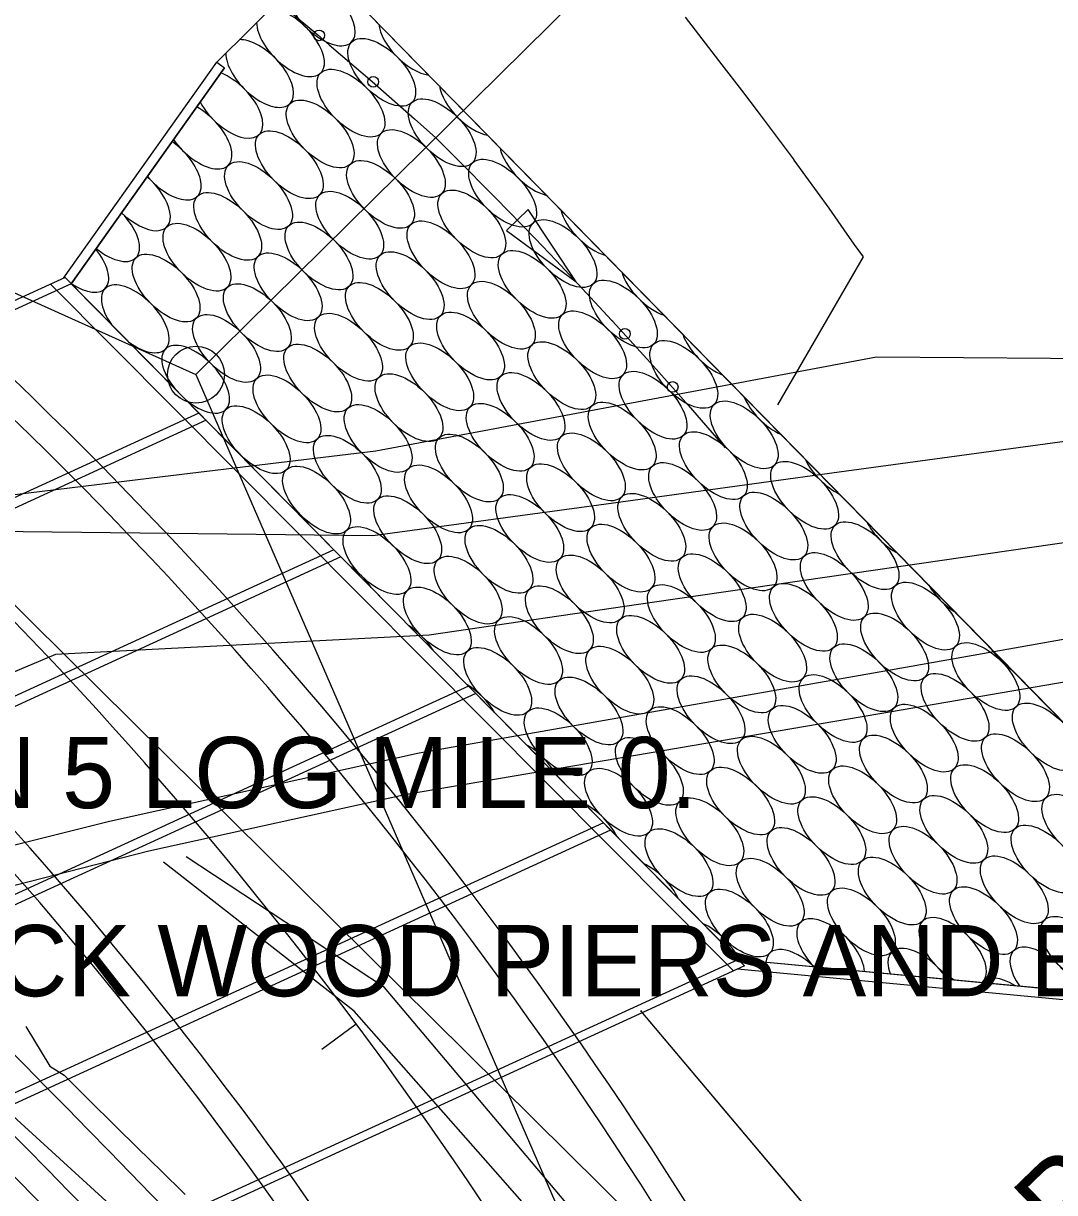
# Model space of a CAD drawing. Extents: x 1660112 to 1662239, y 668919 to 671377.
# Drawn here: x 1661310.6 to 1661383, y 670229.8 to 670311.9 of the extents above; entities that cross this region are included whole.
import ezdxf

# ---------------------------------------------------------------- set-up
doc = ezdxf.new("R2010")
doc.units = 0
for name, color, linetype in [('R_Concrete', 7, 'Continuous'), ('R_Concrete Hidden', 7, 'Continuous'), ('R_Horz Alg', 7, 'Continuous'), ('R_Horz Alg Annot', 7, 'Continuous'), ('R_Proposed Const Limits_Hand', 7, 'Continuous'), ('R_Proposed Road_Lane', 7, 'Continuous'), ('R_Proposed Road_Shoulder', 7, 'Continuous'), ('R_Water', 7, 'Continuous'), ('R_Water Annot', 7, 'Continuous'), ('S_BASELINE', 7, 'Continuous'), ('S_DITCHLINE', 7, 'Continuous'), ('S_EDGE_PAVEMENT', 7, 'Continuous'), ('S_EXIST_ROW', 7, 'Continuous'), ('S_FENCE', 7, 'Continuous'), ('S_LOG_MILE_ANNOT', 7, 'Continuous'), ('S_MSC_PT_SYM', 7, 'Continuous'), ('S_STREAM', 7, 'Continuous'), ('S_SURVEY_TEXT_ANNOT', 7, 'Continuous')]:
    doc.layers.add(name, color=color, linetype=linetype)

msp = doc.modelspace()

# ---------------------------------------------------------------- linework, layer by layer
at = {"layer": 'R_Concrete'}
for p, q in [((1661313.385, 670294.038), (1661324.141, 670309.192)), ((1661313.385, 670294.038), (1661324.141, 670309.192)), ((1661313.922, 670293.642), (1661324.685, 670308.806)), ((1661313.922, 670293.642), (1661324.685, 670308.806)), ((1661324.141, 670309.192), (1661324.685, 670308.806)), ((1661324.141, 670309.192), (1661324.685, 670308.806)), ((1661313.486, 670294.084), (1661236.073, 670258.587)), ((1661313.486, 670294.084), (1661236.073, 670258.587)), ((1661361.211, 670245.744), (1661313.486, 670294.084)), ((1661361.211, 670245.744), (1661313.486, 670294.084)), ((1661312.468, 670293.617), (1661360.441, 670245.391)), ((1661312.468, 670293.617), (1661360.441, 670245.391)), ((1661360.775, 670246.186), (1661389.245, 670243.511)), ((1661360.775, 670246.186), (1661389.245, 670243.511)), ((1661361.211, 670245.744), (1661284.046, 670210.36)), ((1661361.211, 670245.744), (1661284.046, 670210.36)), ((1661360.725, 670245.521), (1661389.183, 670242.848)), ((1661360.725, 670245.521), (1661389.183, 670242.848))]:
    msp.add_line(p, q, dxfattribs=at)
at = {"layer": 'R_Concrete Hidden'}
for p, q in [((1661313.922, 670293.642), (1661236.512, 670258.146)), ((1661313.922, 670293.642), (1661236.512, 670258.146)), ((1661322.894, 670284.555), (1661245.53, 670249.08)), ((1661322.894, 670284.555), (1661245.53, 670249.08)), ((1661323.392, 670284.05), (1661246.031, 670248.577)), ((1661323.392, 670284.05), (1661246.031, 670248.577)), ((1661332.364, 670274.963), (1661255.049, 670239.51)), ((1661332.364, 670274.963), (1661255.049, 670239.51)), ((1661332.863, 670274.458), (1661255.55, 670239.007)), ((1661332.863, 670274.458), (1661255.55, 670239.007)), ((1661341.834, 670265.37), (1661264.569, 670229.941)), ((1661341.834, 670265.37), (1661264.569, 670229.941)), ((1661342.333, 670264.865), (1661265.07, 670229.437)), ((1661342.333, 670264.865), (1661265.07, 670229.437)), ((1661351.305, 670255.778), (1661274.088, 670220.371)), ((1661351.305, 670255.778), (1661274.088, 670220.371)), ((1661351.803, 670255.273), (1661274.589, 670219.867)), ((1661351.803, 670255.273), (1661274.589, 670219.867)), ((1661360.775, 670246.186), (1661283.608, 670210.801)), ((1661360.775, 670246.186), (1661283.608, 670210.801))]:
    msp.add_line(p, q, dxfattribs=at)
at = {"layer": 'R_Horz Alg'}
for centre, radius, start, end in [((1661098.457, 670065.942), 293.82, 23.47166, 65.78059), ((1655846.994, 664877.91), 7639.437, 42.561815, 45.4300379)]:
    msp.add_arc(centre, radius, start, end, dxfattribs=at)
at = {"layer": 'R_Horz Alg Annot'}
for p, q in [((1661218.991, 670333.901), (1661322.681, 670287.259)), ((1661322.681, 670287.259), (1661367.965, 670182.969))]:
    msp.add_line(p, q, dxfattribs=at)
for points in [[(1661322.681, 670287.259), (1661409.789, 670373.237)], [(1661331.524, 670239.885), (1661333.928, 670241.68)]]:
    msp.add_lwpolyline(points, dxfattribs=at)
msp.add_circle((1661322.681, 670287.259), 2, dxfattribs=at)
at = {"layer": 'R_Proposed Const Limits_Hand'}
for points in [[(1661357.049, 670312.358), (1661359.608, 670309.02), (1661360.991, 670307.227), (1661362.161, 670305.69), (1661364.615, 670302.412), (1661364.673, 670302.334), (1661364.68, 670302.324), (1661367.124, 670298.936), (1661368.188, 670297.415), (1661368.881, 670296.416), (1661369.547, 670295.526), (1661363.513, 670285.133)], [(1661310.726, 670241.48), (1661312.417, 670238.696), (1661313.431, 670238.076), (1661314.924, 670236.568), (1661317.231, 670234.267), (1661319.588, 670231.991), (1661320.176, 670231.417), (1661321.933, 670229.691)]]:
    msp.add_lwpolyline(points, dxfattribs=at)
at = {"layer": 'R_Proposed Road_Lane'}
for centre, radius, start, end in [((1661098.457, 670065.942), 303.82, 23.47166, 65.78059), ((1661098.457, 670065.942), 283.82, 24.66292, 65.28151), ((1655846.994, 664877.91), 7650.437, 44.1235183, 45.1360183), ((1655846.994, 664877.91), 7628.437, 44.1235183, 45.1360183)]:
    msp.add_arc(centre, radius, start, end, dxfattribs=at)
at = {"layer": 'R_Proposed Road_Shoulder'}
for centre, radius, start, end in [((1661098.457, 670065.942), 305.82, 23.47166, 65.78059), ((1661098.457, 670065.942), 281.82, 25.82926, 64.17062), ((1655846.994, 664877.91), 7654.437, 44.1235183, 45.1360183), ((1655846.994, 664877.91), 7624.437, 44.1235183, 45.1360183)]:
    msp.add_arc(centre, radius, start, end, dxfattribs=at)
at = {"layer": 'R_Water'}
for p, q in [((1661346.017, 670298.847), (1661344.486, 670297.386)), ((1661346.017, 670298.847), (1661344.486, 670297.386)), ((1661349.394, 670293.776), (1661346.017, 670298.847)), ((1661349.394, 670293.776), (1661346.017, 670298.847)), ((1661344.486, 670297.386), (1661349.394, 670293.776)), ((1661344.486, 670297.386), (1661349.394, 670293.776))]:
    msp.add_line(p, q, dxfattribs=at)
for points in [[(1661329.007, 670312.975), (1661331.235, 670311.111), (1661332.047, 670310.423), (1661335.058, 670307.834), (1661338.041, 670305.208), (1661339.529, 670303.877), (1661339.906, 670303.504), (1661340.933, 670302.484), (1661343.729, 670299.665), (1661346.495, 670296.814), (1661347.974, 670295.264), (1661349.23, 670293.933), (1661351.871, 670291.09), (1661351.934, 670291.022), (1661351.942, 670291.013), (1661354.607, 670288.08), (1661355.781, 670286.768), (1661356.547, 670285.904), (1661357.248, 670285.109), (1661359.857, 670282.109)], [(1661338.845, 670304.489), (1661338.873, 670304.464)], [(1661338.845, 670304.489), (1661338.873, 670304.464)], [(1661338.873, 670304.464), (1661339.529, 670303.877), (1661339.906, 670303.504), (1661340.933, 670302.484), (1661343.729, 670299.665), (1661346.495, 670296.814), (1661347.974, 670295.264), (1661349.23, 670293.933), (1661349.384, 670293.767)], [(1661338.873, 670304.464), (1661339.529, 670303.877), (1661339.906, 670303.504), (1661340.933, 670302.484), (1661343.729, 670299.665), (1661346.495, 670296.814), (1661347.974, 670295.264), (1661349.23, 670293.933), (1661349.384, 670293.767)], [(1661359.416, 670282.616), (1661359.44, 670282.588)], [(1661359.416, 670282.616), (1661359.44, 670282.588)], [(1661359.441, 670282.588), (1661359.857, 670282.109)], [(1661359.441, 670282.588), (1661359.857, 670282.109)]]:
    msp.add_lwpolyline(points, dxfattribs=at)
for centre in [(1661331.33, 670311.078), (1661331.33, 670311.078), (1661335.133, 670307.817), (1661335.133, 670307.817), (1661352.808, 670290.114), (1661352.808, 670290.114), (1661356.162, 670286.392), (1661356.162, 670286.392)]:
    msp.add_circle(centre, 0.375, dxfattribs=at)
at = {"layer": 'R_Water Annot'}
msp.add_lwpolyline([(1661324.141, 670309.192), (1661324.685, 670308.806), (1661313.922, 670293.642), (1661360.775, 670246.186), (1661389.245, 670243.511), (1661389.183, 670242.848), (1661396.368, 670249.803), (1661331.242, 670316.233)], close=True, dxfattribs=at)
msp.add_lwpolyline([(1661385.099, 670261.298), (1661331.242, 670316.233), (1661324.141, 670309.192), (1661324.685, 670308.806), (1661313.922, 670293.642), (1661360.775, 670246.186), (1661389.245, 670243.511), (1661389.183, 670242.848), (1661390.848, 670244.46)], dxfattribs=at)
msp.add_lwpolyline([(1661385.099, 670261.298), (1661331.242, 670316.233), (1661324.141, 670309.192), (1661324.685, 670308.806), (1661313.922, 670293.642), (1661360.775, 670246.186), (1661389.245, 670243.511), (1661389.183, 670242.848), (1661390.848, 670244.46)], dxfattribs=at)
for centre, start_param, end_param in [((1661331.489, 670312.726), 3.617337, 8.876575), ((1661331.489, 670312.726), 3.617337, 8.876575), ((1661329.325, 670310.562), 3.607926, 8.769377), ((1661329.325, 670310.562), 3.607926, 8.769377), ((1661337.895, 670310.647), 3.703494, 5.682404), ((1661337.895, 670310.647), 3.703494, 5.682404), ((1661327.161, 670308.399), 3.598337, 8.674698), ((1661327.161, 670308.399), 3.598337, 8.674698), ((1661327.161, 670308.399), 2.391512, 2.680561), ((1661327.161, 670308.399), 2.391512, 2.680561), ((1661324.997, 670306.235), 4.171264, 8.567811), ((1661324.997, 670306.235), 4.171264, 8.567811), ((1661342.138, 670306.405), 3.750771, 5.635127), ((1661342.138, 670306.405), 3.750771, 5.635127), ((1661322.834, 670304.071), 4.371221, 8.367854), ((1661322.834, 670304.071), 4.371221, 8.367854), ((1661320.67, 670301.907), 4.554184, 8.184891), ((1661320.67, 670301.907), 4.554184, 8.184891), ((1661346.38, 670302.162), 3.799733, 5.586164), ((1661346.38, 670302.162), 3.799733, 5.586164), ((1661318.506, 670299.744), 4.729047, 8.010028), ((1661318.506, 670299.744), 4.729047, 8.010028), ((1661350.623, 670297.919), 3.850708, 5.535189), ((1661350.623, 670297.919), 3.850708, 5.535189), ((1661316.342, 670297.58), 4.901775, 7.837301), ((1661316.342, 670297.58), 4.901775, 7.837301), ((1661314.179, 670295.416), 5.077685, 7.661391), ((1661314.179, 670295.416), 5.077685, 7.661391), ((1661318.421, 670291.174), 4.987016, 10.695869), ((1661318.421, 670291.174), 4.987016, 10.695869), ((1661354.866, 670293.677), 3.904117, 5.48178), ((1661354.866, 670293.677), 3.904117, 5.48178), ((1661359.108, 670289.434), 3.960527, 5.42537), ((1661359.108, 670289.434), 3.960527, 5.42537), ((1661322.664, 670286.931), 4.87823, 10.804655), ((1661322.664, 670286.931), 4.87823, 10.804655), ((1661363.351, 670285.191), 4.020726, 5.365171), ((1661363.351, 670285.191), 4.020726, 5.365171), ((1661324.743, 670280.525), 1.421244, 1.69527), ((1661324.743, 670280.525), 1.421244, 1.69527), ((1661367.593, 670280.949), 4.085877, 5.30002), ((1661367.593, 670280.949), 4.085877, 5.30002), ((1661328.985, 670276.282), 1.294996, 1.821518), ((1661328.985, 670276.282), 1.294996, 1.821518), ((1661371.836, 670276.706), 4.157823, 5.228075), ((1661371.836, 670276.706), 4.157823, 5.228075), ((1661333.228, 670272.039), 1.211455, 1.905059), ((1661333.228, 670272.039), 1.211455, 1.905059), ((1661376.079, 670272.464), 4.239831, 5.146066), ((1661376.079, 670272.464), 4.239831, 5.146066), ((1661337.471, 670267.797), 1.143918, 1.972596), ((1661337.471, 670267.797), 1.143918, 1.972596), ((1661380.321, 670268.221), 4.338878, 5.04702), ((1661380.321, 670268.221), 4.338878, 5.04702), ((1661341.713, 670263.554), 1.085466, 2.031049), ((1661341.713, 670263.554), 1.085466, 2.031049), ((1661345.956, 670259.311), 1.033047, 2.083467), ((1661345.956, 670259.311), 1.033047, 2.083467), ((1661350.199, 670255.069), 0.984996, 2.131518), ((1661350.199, 670255.069), 0.984996, 2.131518), ((1661354.441, 670250.826), 0.940285, 2.17623), ((1661354.441, 670250.826), 0.940285, 2.17623), ((1661358.684, 670246.583), 0.929588, 2.218289), ((1661358.684, 670246.583), 0.929588, 2.218289), ((1661367.254, 670246.668), 0.514314, 4.665033), ((1661367.254, 670246.668), 0.514314, 4.665033), ((1661375.824, 670246.753), 6.231065, 11.514653), ((1661375.824, 670246.753), 6.231065, 11.514653), ((1661373.66, 670244.589), 1.190688, 3.988659), ((1661373.66, 670244.589), 1.190688, 3.988659), ((1661382.231, 670244.674), 0.793691, 4.385656), ((1661382.231, 670244.674), 0.793691, 4.385656), ((1661365.09, 670244.505), 1.619578, 3.559769), ((1661365.09, 670244.505), 1.619578, 3.559769), ((1661380.067, 670242.51), 1.989714, 3.189633), ((1661380.067, 670242.51), 1.989714, 3.189633)]:
    msp.add_ellipse(centre, major_axis=(2.121, -2.121), ratio=0.51, start_param=start_param, end_param=end_param, dxfattribs=at)
for centre in [(1661335.731, 670308.484), (1661335.731, 670308.484), (1661333.567, 670306.32), (1661333.567, 670306.32), (1661339.974, 670304.241), (1661339.974, 670304.241), (1661331.404, 670304.156), (1661331.404, 670304.156), (1661329.24, 670301.992), (1661329.24, 670301.992), (1661337.81, 670302.077), (1661337.81, 670302.077), (1661327.076, 670299.829), (1661327.076, 670299.829), (1661335.646, 670299.913), (1661335.646, 670299.913), (1661344.217, 670299.998), (1661344.217, 670299.998), (1661324.912, 670297.665), (1661324.912, 670297.665), (1661333.483, 670297.75), (1661333.483, 670297.75), (1661342.053, 670297.835), (1661342.053, 670297.835), (1661322.749, 670295.501), (1661322.749, 670295.501), (1661331.319, 670295.586), (1661331.319, 670295.586), (1661339.889, 670295.671), (1661339.889, 670295.671), (1661348.459, 670295.756), (1661348.459, 670295.756), (1661346.295, 670293.592), (1661346.295, 670293.592), (1661320.585, 670293.337), (1661320.585, 670293.337), (1661329.155, 670293.422), (1661329.155, 670293.422), (1661337.725, 670293.507), (1661337.725, 670293.507), (1661326.991, 670291.258), (1661326.991, 670291.258), (1661335.562, 670291.343), (1661335.562, 670291.343), (1661344.132, 670291.428), (1661344.132, 670291.428), (1661352.702, 670291.513), (1661352.702, 670291.513), (1661324.828, 670289.095), (1661324.828, 670289.095), (1661333.398, 670289.18), (1661333.398, 670289.18), (1661341.968, 670289.264), (1661341.968, 670289.264), (1661350.538, 670289.349), (1661350.538, 670289.349), (1661331.234, 670287.016), (1661331.234, 670287.016), (1661339.804, 670287.101), (1661339.804, 670287.101), (1661348.374, 670287.186), (1661348.374, 670287.186), (1661356.944, 670287.27), (1661356.944, 670287.27), (1661329.07, 670284.852), (1661329.07, 670284.852), (1661337.64, 670284.937), (1661337.64, 670284.937), (1661346.211, 670285.022), (1661346.211, 670285.022), (1661354.781, 670285.107), (1661354.781, 670285.107), (1661344.047, 670282.858), (1661344.047, 670282.858), (1661352.617, 670282.943), (1661352.617, 670282.943), (1661361.187, 670283.028), (1661361.187, 670283.028), (1661326.907, 670282.688), (1661326.907, 670282.688), (1661335.477, 670282.773), (1661335.477, 670282.773), (1661333.313, 670280.609), (1661333.313, 670280.609), (1661341.883, 670280.694), (1661341.883, 670280.694), (1661350.453, 670280.779), (1661350.453, 670280.779), (1661359.023, 670280.864), (1661359.023, 670280.864), (1661365.43, 670278.785), (1661365.43, 670278.785), (1661331.149, 670278.446), (1661331.149, 670278.446), (1661339.719, 670278.531), (1661339.719, 670278.531), (1661348.289, 670278.615), (1661348.289, 670278.615), (1661356.86, 670278.7), (1661356.86, 670278.7), (1661337.556, 670276.367), (1661337.556, 670276.367), (1661346.126, 670276.452), (1661346.126, 670276.452), (1661354.696, 670276.536), (1661354.696, 670276.536), (1661363.266, 670276.621), (1661363.266, 670276.621), (1661335.392, 670274.203), (1661335.392, 670274.203), (1661343.962, 670274.288), (1661343.962, 670274.288), (1661352.532, 670274.373), (1661352.532, 670274.373), (1661361.102, 670274.458), (1661361.102, 670274.458), (1661369.672, 670274.542), (1661369.672, 670274.542), (1661350.368, 670272.209), (1661350.368, 670272.209), (1661358.938, 670272.294), (1661358.938, 670272.294), (1661367.509, 670272.379), (1661367.509, 670272.379), (1661341.798, 670272.124), (1661341.798, 670272.124), (1661339.634, 670269.96), (1661339.634, 670269.96), (1661348.205, 670270.045), (1661348.205, 670270.045), (1661356.775, 670270.13), (1661356.775, 670270.13), (1661365.345, 670270.215), (1661365.345, 670270.215), (1661373.915, 670270.3), (1661373.915, 670270.3), (1661371.751, 670268.136), (1661371.751, 670268.136), (1661346.041, 670267.881), (1661346.041, 670267.881), (1661354.611, 670267.966), (1661354.611, 670267.966), (1661363.181, 670268.051), (1661363.181, 670268.051), (1661343.877, 670265.718), (1661343.877, 670265.718), (1661352.447, 670265.803), (1661352.447, 670265.803), (1661361.017, 670265.887), (1661361.017, 670265.887), (1661369.588, 670265.972), (1661369.588, 670265.972), (1661378.158, 670266.057), (1661378.158, 670266.057), (1661350.283, 670263.639), (1661350.283, 670263.639), (1661358.854, 670263.724), (1661358.854, 670263.724), (1661367.424, 670263.809), (1661367.424, 670263.809), (1661375.994, 670263.893), (1661375.994, 670263.893), (1661356.69, 670261.56), (1661356.69, 670261.56), (1661365.26, 670261.645), (1661365.26, 670261.645), (1661373.83, 670261.73), (1661373.83, 670261.73), (1661382.4, 670261.815), (1661382.4, 670261.815), (1661348.12, 670261.475), (1661348.12, 670261.475), (1661354.526, 670259.396), (1661354.526, 670259.396), (1661363.096, 670259.481), (1661363.096, 670259.481), (1661371.666, 670259.566), (1661371.666, 670259.566), (1661380.237, 670259.651), (1661380.237, 670259.651), (1661369.503, 670257.402), (1661369.503, 670257.402), (1661378.073, 670257.487), (1661378.073, 670257.487), (1661352.362, 670257.232), (1661352.362, 670257.232), (1661360.933, 670257.317), (1661360.933, 670257.317), (1661358.769, 670255.154), (1661358.769, 670255.154), (1661367.339, 670255.238), (1661367.339, 670255.238), (1661375.909, 670255.323), (1661375.909, 670255.323), (1661384.479, 670255.408), (1661384.479, 670255.408), (1661356.605, 670252.99), (1661356.605, 670252.99), (1661365.175, 670253.075), (1661365.175, 670253.075), (1661373.745, 670253.16), (1661373.745, 670253.16), (1661382.315, 670253.244), (1661382.315, 670253.244), (1661363.011, 670250.911), (1661363.011, 670250.911), (1661371.582, 670250.996), (1661371.582, 670250.996), (1661380.152, 670251.081), (1661380.152, 670251.081), (1661360.848, 670248.747), (1661360.848, 670248.747), (1661369.418, 670248.832), (1661369.418, 670248.832), (1661377.988, 670248.917), (1661377.988, 670248.917), (1661384.394, 670246.838), (1661384.394, 670246.838)]:
    msp.add_ellipse(centre, major_axis=(2.121, -2.121), ratio=0.51, dxfattribs=at)
at = {"layer": 'S_BASELINE'}
msp.add_line((1660813.757, 670687.354), (1661335.191, 670212.073), dxfattribs=at)
at = {"layer": 'S_DITCHLINE'}
for points in [[(1661494.51, 670072.982), (1661481.632, 670087.012), (1661468.753, 670101.042), (1661468.562, 670102.051), (1661459.49, 670114.585), (1661450.418, 670127.12), (1661437.161, 670141.706), (1661423.904, 670156.292), (1661409.975, 670171.199), (1661396.045, 670186.106), (1661384.955, 670198.234), (1661373.865, 670210.361), (1661354.322, 670219.232), (1661344.063, 670230.901), (1661333.804, 670242.569), (1661320.404, 670253.013)], [(1661495.46, 670073.889), (1661482.853, 670088.246), (1661470.246, 670102.604), (1661470.409, 670103.227), (1661460.798, 670115.596), (1661451.186, 670127.966), (1661437.905, 670142.652), (1661424.623, 670157.339), (1661411.195, 670172.345), (1661397.767, 670187.351), (1661386.715, 670199.361), (1661375.664, 670211.37), (1661356.563, 670219.754), (1661346.237, 670231.986), (1661335.912, 670244.218), (1661322, 670253.404)]]:
    msp.add_lwpolyline(points, dxfattribs=at)
at = {"layer": 'S_EDGE_PAVEMENT'}
msp.add_lwpolyline([(1661528.886, 670006.641), (1661525.806, 670010.935), (1661521.193, 670007.063), (1661512.125, 670017.42), (1661503.057, 670027.777), (1661494.14, 670038.45), (1661485.224, 670049.123), (1661475.652, 670058.134), (1661469.703, 670064.688), (1661453.259, 670082.631), (1661441.578, 670095.542), (1661429.897, 670108.453), (1661415.327, 670123.887), (1661400.757, 670139.321), (1661387.616, 670152.613), (1661374.475, 670165.905), (1661358.805, 670181.905), (1661343.136, 670197.905), (1661339.483, 670201.439), (1661329.75, 670211.046), (1661320.016, 670220.653), (1661304.767, 670236.187)], dxfattribs=at)
at = {"layer": 'S_EXIST_ROW'}
msp.add_line((1661404.925, 670177.113), (1660401.453, 671169.67), dxfattribs=at)
at = {"layer": 'S_FENCE'}
msp.add_line((1661437.439, 670143.547), (1661353.953, 670242.566), dxfattribs=at)
msp.add_lwpolyline([(1661378.505, 670213.446), (1661353.953, 670242.566)], dxfattribs=at)
msp.add_lwpolyline([(1661378.505, 670213.446), (1661353.953, 670242.566)], dxfattribs=at)
at = {"layer": 'S_MSC_PT_SYM'}
msp.add_lwpolyline([(1661353.953, 670242.566), (1661353.953, 670242.617), (1661353.953, 670242.566), (1661353.903, 670242.566), (1661353.953, 670242.566), (1661353.953, 670242.516), (1661353.953, 670242.566), (1661354.003, 670242.566)], dxfattribs=at)
at = {"layer": 'S_STREAM'}
for points in [[(1661620.343, 670335.208), (1661597.17, 670329.748), (1661573.997, 670324.287), (1661550.824, 670318.827), (1661527.651, 670313.366), (1661513.531, 670311.727), (1661499.411, 670310.089), (1661492.641, 670311.04), (1661490.16, 670306.193), (1661483.488, 670303.195), (1661469.163, 670295.943), (1661446.283, 670293.347), (1661423.403, 670290.752), (1661409.166, 670289.526), (1661394.929, 670288.3), (1661370.48, 670288.49), (1661352.895, 670285.184), (1661335.31, 670281.877), (1661320.321, 670280.07), (1661305.333, 670278.263)], [(1661623.558, 670311.06), (1661600.758, 670306.674), (1661577.959, 670302.288), (1661555.159, 670297.902), (1661532.36, 670293.515), (1661508.209, 670288.486), (1661492.784, 670284.301), (1661477.359, 670280.116), (1661459.421, 670277.44), (1661441.483, 670274.763), (1661423.546, 670272.087), (1661405.608, 670269.41), (1661388.574, 670266.498), (1661371.539, 670263.586), (1661354.505, 670260.675), (1661337.471, 670257.763), (1661319.369, 670253.79), (1661298.791, 670248.535)], [(1661384.222, 670282.639), (1661367.853, 670280.404), (1661351.484, 670278.169), (1661335.115, 670275.934), (1661320.767, 670276.104), (1661306.42, 670276.273), (1661294.473, 670269.731), (1661282.527, 670263.188), (1661272.558, 670254.422), (1661262.589, 670245.657), (1661251.645, 670237.737), (1661240.701, 670229.817), (1661218.363, 670218.702), (1661205.188, 670219.729), (1661192.013, 670220.756), (1661178.838, 670221.783), (1661165.663, 670222.81), (1661153.899, 670226.651)], [(1661386.076, 670275.795), (1661370.403, 670273.521), (1661354.731, 670271.246), (1661339.058, 670268.971), (1661325.94, 670268.284), (1661312.823, 670267.597), (1661300.918, 670262.594), (1661289.014, 670257.591), (1661278.505, 670249.411), (1661267.997, 670241.23), (1661256.407, 670232.402), (1661244.816, 670223.573), (1661232.524, 670217.574), (1661220.231, 670211.575), (1661206.017, 670213.108), (1661191.802, 670214.641), (1661177.588, 670216.175), (1661163.373, 670217.708), (1661152.073, 670221.36)], [(1661387.417, 670269.332), (1661371.062, 670266.445), (1661354.707, 670263.558), (1661338.352, 670260.672), (1661316.604, 670255.879), (1661296.46, 670250.856), (1661285.678, 670241.855), (1661274.895, 670232.855), (1661258.896, 670220.776), (1661250.843, 670216.603), (1661237.043, 670210.679), (1661223.242, 670204.755), (1661207.848, 670205.503), (1661192.454, 670206.252), (1661177.059, 670207), (1661161.665, 670207.749), (1661149.8, 670215.109)]]:
    msp.add_lwpolyline(points, dxfattribs=at)

# ---------------------------------------------------------------- texts
at = {"layer": 'R_Horz Alg Annot'}
msp.add_text('PI  111+42.05', height=6, rotation=43.99593, dxfattribs=at).set_placement((1661383.83, 670225.4))
at = {"layer": 'S_LOG_MILE_ANNOT'}
msp.add_text('ROUTE 90 SECTION 5 LOG MILE 0.', height=5, dxfattribs=at).set_placement((1661247.152, 670256.815))
at = {"layer": 'S_SURVEY_TEXT_ANNOT'}
msp.add_text('CONC DECK WOOD PIERS AND BEAMS', height=5, dxfattribs=at).set_placement((1661277.994, 670243.609))

doc.saveas('drawing.dxf')
